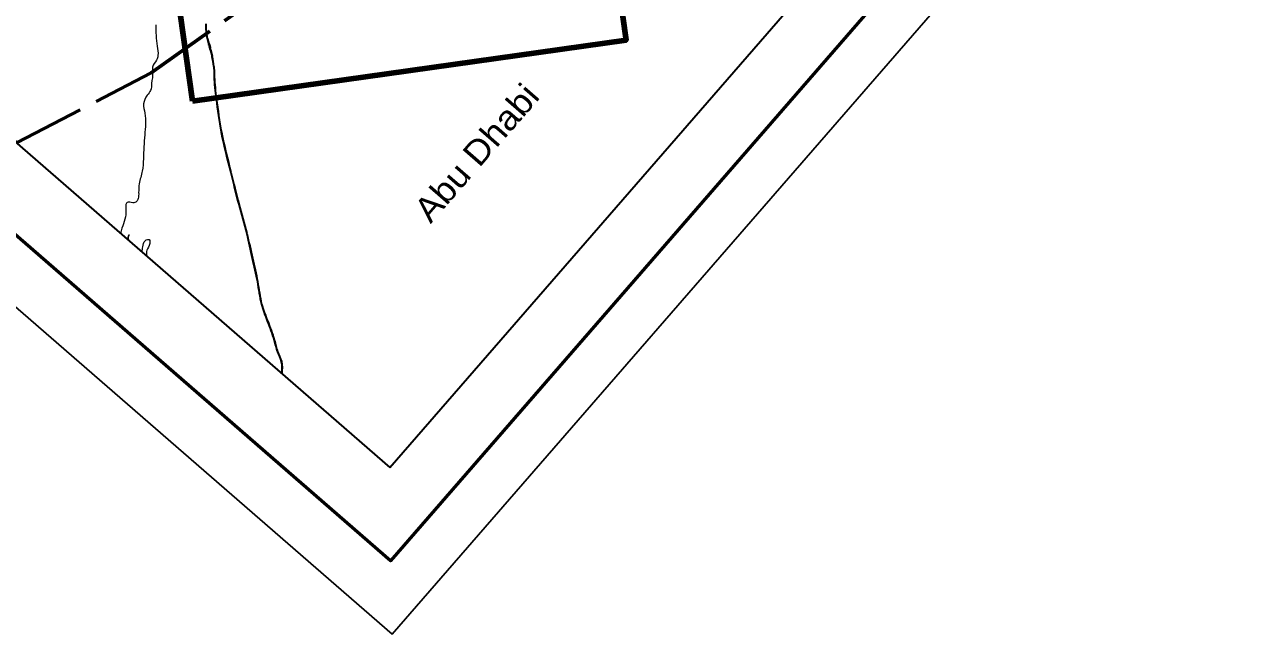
# Model space of a CAD drawing. Extents: x 290038 to 370218, y 2722677 to 2808586.
# Drawn here: x 318589 to 327675, y 2722677 to 2727151 of the extents above; entities that cross this region are included whole.
import ezdxf

# ---------------------------------------------------------------- set-up
doc = ezdxf.new("R2010")
doc.units = 0
doc.header["$LTSCALE"] = 88
doc.linetypes.add('LONG_DASHED', pattern=[7.5, 6, -1.5])
for name, color, linetype, lineweight in [('20', 7, 'Continuous', 13), ('25', 7, 'Continuous', 13), ('3', 7, 'Continuous', 13), ('36', 7, 'Continuous', 35), ('6', 7, 'Continuous', 13), ('63', 7, 'Continuous', 35), ('7', 7, 'LONG_DASHED', 60)]:
    doc.layers.add(name, color=color, linetype=linetype, lineweight=lineweight)

msp = doc.modelspace()

# ---------------------------------------------------------------- linework, layer by layer
at = {"layer": '20', "lineweight": 25}
for points in [[(313980.4, 2729027.31), (362912.77, 2785317.56), (370218.38, 2778966.9), (321286.01, 2722676.64)], [(321270.19, 2723900.42), (327462.36, 2731023.7), (321446.7, 2736253.03), (315254.53, 2729129.75)]]:
    msp.add_lwpolyline(points, close=True, dxfattribs=at)
at = {"layer": '20', "lineweight": 53}
msp.add_lwpolyline([(314544.71, 2729066.77), (349767.76, 2769586.26), (356498.65, 2763735.18), (321275.6, 2723215.69)], close=True, dxfattribs=at)
at = {"layer": '25', "lineweight": 90}
msp.add_lwpolyline([(319820.39, 2726590.27), (318886.16, 2733237.63), (322070.51, 2733685.16), (323004.74, 2727037.81)], close=True, dxfattribs=at)
at = {"layer": '3'}
msp.add_line((319291.92, 2725620.1), (319484.4, 2725452.78), dxfattribs=at)
msp.add_lwpolyline([(319484.4, 2725452.78), (315254.53, 2729129.75), (319091.4, 2733543.57)], dxfattribs=at)
msp.add_spline([(319551.66, 2727150.69), (319560.92, 2726992.58), (319567.23, 2726923.89), (319556.87, 2726891.62), (319528.08, 2726840.44), (319528.65, 2726801.48), (319521.03, 2726720.63), (319513.38, 2726669.02), (319488.63, 2726632.68), (319462.1, 2726570.25), (319471.65, 2726501.75), (319470.03, 2726343.26), (319460.47, 2726167.26), (319451.77, 2726076.6), (319430.22, 2725983.58), (319425.77, 2725918.34), (319422.53, 2725875.11), (319410, 2725852.46), (319383.69, 2725843.66), (319340.56, 2725845.27), (319331.18, 2725824.43), (319332.33, 2725789.56), (319303.25, 2725657.13), (319291.92, 2725620.1)], degree=3, dxfattribs=at)
at = {"layer": '36'}
for p, q in [((319930.33, 2727043.4), (319964.36, 2726918.65)), ((319931.46, 2727043.7), (319937.9, 2727020.1)), ((319940.97, 2727012.3), (319950.14, 2726979.68)), ((319945.03, 2727005.21), (319950.48, 2726985.82)), ((319943.43, 2726983.98), (319946.81, 2726983.17)), ((319952.25, 2726967.51), (319965.5, 2726918.96)), ((319976.5, 2726844.2), (319979.71, 2726801.62)), ((319977.68, 2726844.29), (319980.88, 2726801.71))]:
    msp.add_line(p, q, dxfattribs=at)
for centre, radius, start, end in [((320337.49, 2727142.72), 419.31, 178.14472, 188.79612), ((320337.49, 2727142.72), 418.18, 178.14472, 188.79612), ((320145.11, 2727105.79), 223.66, 186.98388, 196.19951), ((320145.11, 2727105.79), 222.49, 186.98388, 196.19951), ((320708.39, 2727342.26), 835.13, 202.69099, 202.97485), ((319944.33, 2727001.69), 5.6, 135.66394, 186.1467), ((319930.03, 2727010.55), 11.08, 9.08175, 31.16101), ((319942.64, 2727004.99), 2.4, 5.25844, 165.20428), ((319943.5, 2726985.86), 1.88, 189.50658, 267.83009), ((319948.3, 2726984.77), 2.42, 241.76645, 25.81613), ((319934.26, 2726974.17), 16.82, 2.02996, 19.1395), ((319893.41, 2726961.59), 59.14, 5.74815, 12.87373), ((319596.03, 2726820.36), 381.23, 3.58629, 14.94186), ((319596.03, 2726820.36), 382.4, 3.58629, 14.94186)]:
    msp.add_arc(centre, radius, start, end, dxfattribs=at)
for points in [[(319979.71, 2726801.7), (319980.03, 2726769.46), (319994.79, 2726608.57), (320032.3, 2726361.24), (320101.79, 2726065.39), (320160.28, 2725834.76), (320218.8, 2725617.96), (320259.88, 2725436.75), (320297.17, 2725265.05), (320327.64, 2725099.38), (320370.33, 2724976.62), (320420.54, 2724834.92), (320444.82, 2724750.18), (320472.4, 2724677.97), (320475.45, 2724591.27)], [(319980.88, 2726801.71), (319981.2, 2726769.52), (319995.96, 2726608.71), (320033.46, 2726361.46), (320102.93, 2726065.67), (320161.42, 2725835.05), (320219.94, 2725618.24), (320261.03, 2725437), (320298.32, 2725265.29), (320328.78, 2725099.68), (320371.44, 2724977.01), (320421.66, 2724835.27), (320445.93, 2724750.55), (320473.57, 2724678.2), (320476.62, 2724590.26)]]:
    msp.add_spline(points, degree=3, dxfattribs=at)
at = {"layer": '6', "lineweight": 35}
msp.add_lwpolyline([(321270.19, 2723900.42), (327462.36, 2731023.7), (321446.7, 2736253.03), (315254.53, 2729129.75)], close=True, dxfattribs=at)
at = {"layer": '6'}
for points in [[(319551.66, 2727150.69), (319560.92, 2726992.58), (319567.23, 2726923.89), (319556.87, 2726891.62), (319528.08, 2726840.44), (319528.65, 2726801.48), (319521.03, 2726720.63), (319513.38, 2726669.02), (319488.63, 2726632.68), (319462.1, 2726570.25), (319471.65, 2726501.75), (319470.03, 2726343.26), (319460.47, 2726167.26), (319451.77, 2726076.6), (319430.22, 2725983.58), (319425.77, 2725918.34), (319422.53, 2725875.11), (319410, 2725852.46), (319383.69, 2725843.66), (319340.56, 2725845.27), (319331.18, 2725824.43), (319332.33, 2725789.56), (319303.25, 2725657.13), (319291.92, 2725620.1)], [(319342.45, 2725576.18), (319354.75, 2725608.07), (319353.99, 2725607.21), (319349.62, 2725569.94)], [(319450.3, 2725482.43), (319450.93, 2725486.82), (319456.34, 2725520.43), (319474.83, 2725566.97), (319502.85, 2725574.25), (319502.84, 2725531.19), (319483.49, 2725485.42), (319484.4, 2725452.78)]]:
    msp.add_spline(points, degree=3, dxfattribs=at)
at = {"layer": '63', "linetype": 'LONG_DASHED', "lineweight": 60}
msp.add_lwpolyline([(319516.82, 2726796.88), (320616.88, 2727578.1), (322564.47, 2727360.23), (323266.05, 2727344.22), (324279.08, 2727864.81), (324324.42, 2727927.95), (325249.5, 2729382.41), (325228.96, 2729972.67), (325230.9, 2730287), (325311.72, 2730349.11), (325554.8, 2730923.68), (325801.55, 2731536.78), (325592.92, 2731637.35)], dxfattribs=at)
at = {"layer": '7'}
msp.add_lwpolyline([(318633.57, 2733016.88), (315254.53, 2729129.75), (318527.96, 2726284.21), (319516.82, 2726796.88), (320616.88, 2727578.1), (322564.47, 2727360.23), (323266.05, 2727344.22), (324279.08, 2727864.81)], dxfattribs=at)

# ---------------------------------------------------------------- texts
at = {"layer": '25', "width": 1.1}
msp.add_text('Abu Dhabi', height=180, rotation=49, dxfattribs=at).set_placement((321568.86, 2725685.3))

doc.saveas('drawing.dxf')
